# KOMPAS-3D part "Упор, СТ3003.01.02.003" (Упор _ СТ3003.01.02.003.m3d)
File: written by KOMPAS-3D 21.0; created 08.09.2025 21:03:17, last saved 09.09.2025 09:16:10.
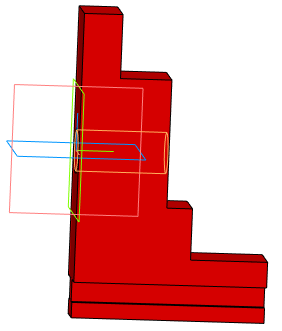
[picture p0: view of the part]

Document properties: Полное имя файла: C:\Users\1\Yandex.Disk\Документы\Новая папка\Стапель №2\Стапель _ СТ3003.00.00.000\Опора _ СТ3003.01.00.000\3D\Кронштейн _ СТ3003.01.02.000\Упор _ СТ3003.01.02.003.m3d

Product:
- Part/product: Упор  | designation СТ3003.01.02.003
    Материал: Сталь 45  ГОСТ 1050-2013 (density 7810 kg/m3)
    Масса: 0.784266
    Форматы листов документа: A3

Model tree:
1. Эскиз:1
2. Элемент выдавливания:1
     Расстояние 1 = 75
3. Эскиз:2  (with: Элемент выдавливания:1)
4. Элемент выдавливания:2
     Расстояние 2 = 25
5. Эскиз:3  (with: Элемент выдавливания:1)
6. Элемент выдавливания:3
     Расстояние 2 = 75
7. Условное изображение резьбы:1  (with: Элемент выдавливания:3)  (labels: M16; cil0_24705-2004 coarse)
     Длина резьбы = 35; Шаг резьбы = 2; Номинальный диаметр резьбы = 16
8. Подгонка:1  (with: Элемент выдавливания:3)
9. Фаска:1  (with: Элемент выдавливания:3)  (labels: Сталь 45  ГОСТ 1050-2013)
     Угол = 45; Длина 1 = 2; Длина 2 = 2

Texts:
  СТ3003.01.02.003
